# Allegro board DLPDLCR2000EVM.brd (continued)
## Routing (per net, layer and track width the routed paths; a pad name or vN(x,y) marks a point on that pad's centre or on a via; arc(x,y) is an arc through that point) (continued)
DATEN: length 43
  TOP w0.132: v2(24.5,33.76) 24.5,33.76 24.7,33.96 24.7,37.07 26.29,38.66 28.76,38.66 28.82,38.73 U12.G15
  BOTTOM w0.132: v2(24.5,33.76) 25.89,33.76 25.9,33.75 27.02,33.75 27.22,33.94 28.69,33.94 29.34,33.29 34.36,33.29 40.61,39.55 40.61,46.25 44.15,49.78 44.15,51.61 45.14,52.6 P1.30
DBIC_CSZ: length 6.3
  LY2 w0.102: 31.8,35.56 31.51,35.85 v1(31.51,36.73)
  LY2 w0.132: v3(31.51,34.44) 31.89,34.83 31.89,35.47 31.8,35.56
  LY3 w0.132: v4(31.5,31.32) 31.54,31.32 32.21,31.99 32.21,32.84 31.51,33.54 v3(31.51,34.44)
DMD_BUS: length 22.3
  TOP w0.132: R37.1 24.77,40.34 v4(24.51,40.08) ; v4(22.74,32.31) 22.6,32.16 J1.27
  LY3 w0.132: v4(22.74,32.31) 22.81,32.37 22.81,33.15 23.02,33.36 23.02,36.3 22.77,36.54 22.77,37.12 22.61,37.28 22.32,37.28 22.18,37.15 22.18,35.89 22.21,35.86 22.21,35.67 22.08,35.53 21.89,35.53 21.78,35.65 21.78,37.84 21.69,37.92 21.46,37.92 21.32,37.79 21.32,37.51 21.33,37.51 21.33,35.54 21.2,35.41 21.01,35.41 20.88,35.54 20.88,37.92 21.89,38.94 21.89,39.32 22.16,39.59 24.01,39.59 v4(24.51,40.08)
DMD_BUS_T: length 5.4
  LY3 w0.102: 28.73,40.11 28.81,40.11 28.93,39.99 29.97,39.99 v4(30.31,40.33)
  LY3 w0.132: v4(25.32,40.54) 28.24,40.54 28.67,40.11 28.73,40.11
DMD_D0: length 31.7
  TOP w0.132: v4(19.99,32.46) 17.86,32.46 17.65,32.66 J1.26 ; v4(22.53,33.4) 22.91,33.4 23.5,33.99 23.5,34.26 24.31,35.08 24.31,39.81 24.03,40.09 24.03,41.38 22.35,43.05 22.35,46.72 22.49,46.85 24.63,46.85 24.76,46.72 24.76,45.38 24.63,45.25 24.5,45.25 24.22,45.25 23.59,44.61 23.59,43.43 23.83,43.19 23.83,42.29 24.51,41.61 R11.1
  LY3 w0.132: v4(22.53,33.4) 20.93,33.4 v4(19.99,32.46)
DMD_D0_T: length 3.1
  TOP w0.132: R11.2 27.97,41.61 28.84,40.73 U12.M15
DMD_D1: length 22.4
  TOP w0.132: v4(20.87,39.18) 18.53,39.18 17.91,39.8 16.84,39.8 16.69,39.65 16.69,39.18 16.83,39.05 16.99,39.05 17.04,38.99 17.67,38.99 17.81,38.86 17.81,38.35 17.62,38.16 J1.4
  LY3 w0.132: v4(24.77,42.67) 24.77,42.44 24.59,42.27 23.93,42.27 23.8,42.13 23.8,40.17 23.71,40.08 23.52,40.08 23.43,40.17 23.43,42.53 23.98,43.08 23.98,44.14 23.85,44.27 23.47,44.27 22.61,43.41 22.61,41.29 21.3,39.98 21.3,39.85 20.87,39.42 v4(20.87,39.18)
DMD_D1_T: length 5.2
  LY3 w0.132: v4(29.91,41.13) 29.38,41.13 28.73,41.78 26.88,41.78 26.71,41.95 26.05,41.95 v4(25.32,42.67)
DMD_D2: length 22.9
  TOP w0.132: v4(19.94,36.86) 19.9,36.82 19.24,36.82 18.47,37.59 17.96,37.59 17.53,37.16 16.83,37.16 J1.8
  LY3 w0.132: v4(24.77,41.96) 24.23,41.96 24.08,41.81 24.08,40 23.91,39.83 23.32,39.83 23.18,39.97 23.18,42.64 23.73,43.18 23.73,43.71 23.6,43.85 23.4,43.85 23.29,43.74 23.29,43.31 22.85,42.88 22.85,41.19 21.54,39.88 21.54,39.75 21.21,39.41 21.21,38.96 20.29,38.05 20.14,38.05 19.94,37.85 19.94,37.54 20.35,37.13 20.35,35.89 20.21,35.76 19.94,35.76 19.8,35.89 19.8,36.24 19.94,36.37 v4(19.94,36.86)
DMD_D2_T: length 5.1
  LY3 w0.132: v4(25.32,41.96) 25.58,41.7 26.61,41.7 26.78,41.53 28.52,41.53 29.21,40.84 29.59,40.84 29.71,40.73 v4(29.91,40.73)
DMD_D3: length 24.3
  TOP w0.132: v4(26.19,42.32) 24.41,42.32 24.21,42.52 24.21,42.73 v4(24.12,42.81) ; J1.12 17.42,36.16 17.86,36.6 17.92,36.6 18.03,36.71 18.03,37.01 18.13,37.11 18.31,37.11 18.44,36.97 18.44,36.73 18.62,36.56 19.03,36.56 19.11,36.47 v4(19.59,36.47)
  LY3 w0.132: v4(19.59,36.47) 19.58,36.48 19.58,39.95 19.69,40.06 20,40.06 20.09,40.16 20.09,40.28 19.91,40.45 19.91,40.64 20.04,40.77 20.24,40.77 20.42,40.59 20.6,40.59 20.7,40.69 20.7,40.82 20.82,40.93 20.99,40.93 21,40.94 21.01,40.94 21.13,40.82 21.13,40.69 21.27,40.55 21.45,40.55 21.56,40.67 21.56,40.94 21.67,41.05 22.01,41.05 22.36,41.4 22.36,43.52 23.63,44.8 23.75,44.8 23.93,44.61 24.04,44.61 24.11,44.69 24.11,44.79 23.94,44.96 23.94,45.11 24.05,45.21 24.13,45.21 24.26,45.09 24.44,45.09 24.75,45.39 24.94,45.39 25.03,45.3 25.03,45.13 24.22,44.32 24.22,43.44 24.46,43.21 24.46,42.68 24.32,42.55 24.18,42.55 24.12,42.6 v4(24.12,42.81)
DMD_D3_T: length 3.3
  TOP w0.132: U12.N15 28.92,41.13 27.73,42.32 R10.2
DMD_D4: length 27.9
  TOP w0.132: v4(20.04,35.33) 19.99,35.38 17.81,35.38 17.52,35.66 J1.14 ; R13.1 27.41,45.67 27.06,45.67 26.8,45.41 26.8,45.2 26.3,44.7 26.07,44.7 25.77,45 25.77,47.56 25.45,47.88 21.69,47.88 21.35,47.53 21.35,42.64 22.89,41.09 v4(22.89,40.81)
  LY3 w0.132: v4(22.89,40.81) 22.89,40.54 22.78,40.44 22.61,40.44 21.56,39.4 21.56,38.96 20.62,38.02 20.62,35.53 20.42,35.33 v4(20.04,35.33)
DMD_D4_T: length 5.1
  LY3 w0.102: 29.16,42.67 v4(30.31,41.53)
  LY3 w0.132: v4(27.89,45.59) 27.89,43.95 29.16,42.67
DMD_D5: length 24
  TOP w0.132: v4(19.66,34.98) 19.64,35 18.91,35 18.84,34.92 18.84,34.59 18.76,34.52 18.65,34.52 18.58,34.59 18.58,34.9 18.5,34.98 18.39,34.98 18.32,34.9 18.32,34.59 18.24,34.52 18.01,34.52 17.88,34.65 17.88,34.98 17.81,35.05 17.67,35.05 17.55,35.16 J1.16
  LY3 w0.132: v4(24.77,43.38) 24.47,43.68 24.47,44.22 25.34,45.09 26.11,45.09 26.24,45.22 26.24,45.47 26.07,45.64 24.13,45.64 22.11,43.63 22.11,41.54 21.88,41.31 21.02,41.31 20.89,41.18 20.07,41.18 19.3,40.41 19.3,36.33 19.53,36.09 19.53,35.89 19.36,35.72 19.36,35.16 19.54,34.98 v4(19.66,34.98)
DMD_D5_T: length 5.4
  LY2 w0.102: v1(29.91,41.53) v3(29.41,41.53)
  LY3 w0.132: v4(25.32,43.38) 25.63,43.38 26.92,42.09 28.85,42.09 v3(29.41,41.53)
DMD_D6: length 30.8
  TOP w0.132: v4(19.13,32.82) 18.08,32.82 17.73,33.17 16.83,33.17 J1.24 ; v4(22.63,34.62) 22.63,34.62 23.21,34.62 23.98,35.38 23.98,39.62 23.72,39.88 23.72,39.92 23.69,39.95 23.69,41.24 22.02,42.91 22.02,47.05 22.15,47.18 24.94,47.18 25.1,47.02 25.1,45.04 24.97,44.91 24.36,44.91 23.92,44.47 23.92,43.57 24.46,43.03 R9.1
  LY3 w0.132: v4(22.63,34.62) 21.51,34.62 19.71,32.82 v4(19.13,32.82)
DMD_D6_T: length 3.4
  TOP w0.132: R9.2 27.49,43.03 28.99,41.53 U12.P15
DMD_D7: length 30.3
  TOP w0.132: R8.1 24.48,43.74 24.26,43.96 24.26,44.34 24.5,44.58 25.23,44.58 25.43,44.78 25.43,47.16 25.07,47.52 21.86,47.52 21.68,47.34 21.68,42.78 23.36,41.1 23.36,39.81 23.39,39.78 23.39,39.74 23.39,39.73 23.39,39.72 23.63,39.48 23.63,36 22.76,35.13 v4(22.66,35.13) ; J1.20 16.83,34.16 17.65,34.16 18.03,33.78 v4(19.25,33.78)
  LY3 w0.132: v4(19.25,33.78) 19.25,34.01 20.27,35.03 22.56,35.03 v4(22.66,35.13)
DMD_D7_T: length 3.5
  TOP w0.132: R8.2 27.25,43.74 29.07,41.93 U12.R15
DMD_D8: length 25.9
  TOP w0.132: J1.7 19.43,37.16 18.62,37.97 v4(18,37.97)
  LY3 w0.132: v4(28.96,44.73) 28.96,44.5 29.31,44.14 29.31,43.62 29.18,43.48 28.71,43.48 28.3,43.9 28.3,46.38 27.8,46.87 23.52,46.87 20.78,44.13 20.78,42.81 20.47,42.49 19.61,42.49 19.32,42.2 18.74,42.2 18,41.47 v4(18,37.97)
DMD_D8_T: length 3.3
  TOP w0.132: R16.2 28.96,43.71 29.43,43.24 30.02,43.24 30.71,42.55 U12.R12
DMD_D9: length 23.5
  TOP w0.132: v4(17.12,39.37) 17.83,39.37 19.04,38.16 J1.3
  LY3 w0.132: v4(30.02,46.15) 28.43,47.75 23.34,47.75 19.93,44.35 19.35,44.35 17.12,42.11 v4(17.12,39.37)
DMD_D9_T: length 6.5
  LY3 w0.102: 31.05,42.67 31.05,42.5 31.29,42.25 31.29,42.22 31.35,42.16 31.35,41.9 31.39,41.86 31.39,41.41 31.11,41.13 v4(31.11,41.13)
  LY3 w0.132: v4(30.02,45.59) 30.39,45.96 30.96,45.96 31.1,45.81 31.1,45.5 31.09,45.49 31.09,45.24 30.79,44.94 30.79,44.05 31.05,43.79 31.05,42.67
DMD_D10: length 24.8
  TOP w0.132: J1.13 21.08,35.66 21.03,35.72 18.03,35.72 v4(18.01,35.74)
  LY3 w0.132: v4(18.01,35.74) 17.42,36.32 17.42,41.83 18.29,42.7 19.05,42.7 19.99,43.64 19.99,44.05 23.3,47.37 28.1,47.37 v4(29.31,46.15)
DMD_D10_T: length 4.8
  LY3 w0.102: v4(31.11,41.53) 30.48,42.16 30.48,42.67
  LY3 w0.132: 30.48,42.67 30.48,43.67 30.02,44.13 30.02,44.89 v4(29.31,45.59)
DMD_D11: length 25.7
  TOP w0.132: v4(18.02,36.25) 18.11,36.25 18.14,36.22 18.89,36.22 18.99,36.12 19.71,36.12 19.81,36.22 21.47,36.22 J1.11
  LY3 w0.132: v4(18.02,36.25) 18.07,36.25 18.07,36.24 17.92,36.24 17.68,36.47 17.68,41.61 18.52,42.45 19.18,42.45 19.48,42.75 20.37,42.75 20.54,42.92 20.54,44.24 23.42,47.12 27.9,47.12 29,46.02 29,45.4 29.14,45.27 29.18,45.27 29.67,44.78 v4(29.67,44.73)
DMD_D11_T: length 3
  TOP w0.132: R18.2 29.67,43.84 29.9,43.61 30.12,43.61 31.11,42.63 U12.R11
DMD_D12: length 37
  LY3 w0.132: v2(18.15,28.38) 18.62,28.85 18.62,31.39 16.21,33.81 16.21,43.54 18.77,46.1 19.88,46.1 20.49,46.71 22.27,48.49 29.57,48.49 31.35,46.71 31.35,45.4 31.34,45.39 31.34,45.1 31.09,44.85 v4(31.09,44.73)
  BOTTOM w0.132: R105.2 v2(18.15,28.38)
DMD_D12_OPT: length 2.9
  TOP w0.132: J1.44 v2(15.24,28.16)
  BOTTOM w0.132: v2(15.24,28.16) 16.07,28.16 16.29,28.38 R105.1
DMD_D12_T: length 3.3
  LY3 w0.102: v4(31.51,41.13) 31.51,41.25 31.59,41.33 31.59,41.95 31.56,41.98 31.56,42.28 31.3,42.54 31.3,42.67
  LY3 w0.132: 31.3,42.67 31.3,43.96 v4(31.09,44.17)
DMD_D13: length 35.2
  TOP w0.132: v4(30.77,46.79) 30.77,46.74 30.78,46.73 R21.1
  LY3 w0.132: v2(18.16,27.66) 18.9,28.4 18.9,31.57 16.48,33.99 16.48,43.31 19.01,45.83 20.08,45.83 22.49,48.24 29.32,48.24 v4(30.77,46.79)
  BOTTOM w0.132: R106.2 v2(18.16,27.66)
DMD_D13_OPT: length 1.8
  TOP w0.132: J1.46 v2(15.75,27.66)
  BOTTOM w0.132: R106.1 16.47,27.66 v2(15.75,27.66)
DMD_D13_T: length 4.6
  LY2 w0.102: v3(31.01,42.14) 31.01,42.02 v1(31.51,41.53)
  LY3 w0.132: v3(31.01,42.14) 30.81,42.35 30.81,43.69 30.55,43.95 30.55,45.41 30.73,45.59 v4(30.78,45.59)
DMD_D14: length 36.3
  TOP w0.132: v4(30.14,46.77) 30.38,46.54 30.38,46.41 30.38,46.41 30.38,45.89 30.38,45.89 30.38,45.85 30.38,45.85 30.38,45.34 30.38,45.33 R20.1
  LY3 w0.132: v4(30.14,46.77) 28.92,48 22.59,48 20.18,45.59 19.27,45.59 16.74,43.05 16.74,34.14 19.18,31.7 19.18,27.97 v2(18.15,26.94)
  BOTTOM w0.132: R113.2 v2(18.15,26.94)
DMD_D14_OPT: length 3
  TOP w0.132: J1.48 v2(15.21,27.16)
  BOTTOM w0.132: v2(15.21,27.16) 15.44,26.94 R113.1
DMD_D14_T: length 2.7
  TOP w0.132: R20.2 30.38,43.84 31.51,42.71 U12.R10
DMD_DCLK: length 22.2
  TOP w0.132: J1.17 v4(19.25,34.66)
  LY3 w0.132: v4(19.25,34.66) 19.23,34.66 19.05,34.85 19.05,40.57 19.71,41.22 19.73,41.22 19.93,41.42 20.79,41.42 21,41.63 21.77,42.41 21.77,43.64 24.02,45.89 26.17,45.89 26.42,45.64 26.7,45.64 26.87,45.48 26.87,45.18 26.87,45.18 26.87,44.96 26.72,44.81 25.48,44.81 v4(24.77,44.09)
DMD_DCLK_T: length 6.2
  LY3 w0.102: 28.73,42.39 29.04,42.39 v4(30.31,41.13)
  LY3 w0.132: 28.73,42.39 27.18,42.39 25.48,44.09 v4(25.32,44.09)
DMD_LOADB: length 26.4
  TOP w0.132: v4(27.17,45.23) 27.17,45.23 27.17,45.14 27.18,45.13 28.11,45.13 28.24,44.99 R14.1 ; 20.13,34.16 20.13,34.17 v2(20.13,34.17) ; 20.13,34.16 v4(18.42,34.16) ; 20.13,34.16 J1.19
  LY3 w0.132: v4(18.42,34.16) 18.42,33.78 18.31,33.68 18.17,33.68 18.03,33.81 18.03,34.8 18.56,35.32 18.56,41.17 19.11,41.71 19.52,41.71 19.73,41.92 20.59,41.92 21.28,42.61 21.28,43.88 21.42,44.02 23.78,46.38 27.03,46.38 27.17,46.25 27.17,45.23 v4(27.17,45.23)
  BOTTOM w0.132: v2(20.13,34.17) 20.13,34.17 20.13,34.16 R109.1
DMD_LOADB_T: length 3.6
  TOP w0.132: U12.R13 30.31,42.46 29.87,42.9 29.04,42.9 28.24,43.7 R14.2
DMD_OEZ: length 30.1
  TOP w0.132: v2(23.24,30.15) 23.23,30.16 J1.35
  LY3 w0.102: v4(30.31,40.73) 30.3,40.73 29.77,40.19 29.02,40.19 28.73,40.48
  LY3 w0.132: v2(23.24,30.15) 23.55,29.84 23.55,28.97 23.47,28.9 22.55,28.9 22.48,28.82 22.48,28.71 22.55,28.64 23.47,28.64 23.55,28.56 23.55,28.02 23.74,27.82 23.93,27.82 25.05,28.94 25.05,32.4 24.9,32.56 24.29,32.56 23.77,33.08 23.77,37.21 22.86,38.13 22.86,38.72 22.99,38.85 24.62,38.85 25.16,39.39 25.16,40.19 25.03,40.32 25.03,40.66 25.2,40.83 28.38,40.83 28.73,40.48
  BOTTOM w0.132: v2(23.24,30.15) 23.23,30.16 21.9,30.16 R108.1
DMD_SAC_BUS: length 24.6
  TOP w0.132: v4(23.39,32.65) 23.38,32.66 23.19,32.66 23.09,32.56 23.09,31.3 22.96,31.16 J1.31 ; R38.1 26.19,40.84 25.86,40.51 25.86,40.43 25.56,40.13 25.48,40.13 v4(24.86,39.51)
  LY3 w0.132: v4(23.39,32.65) 23.33,32.58 23.33,31 23.8,30.53 23.8,28.58 23.93,28.45 24.19,28.45 24.81,29.07 24.81,32.16 24.66,32.31 23.91,32.31 23.77,32.44 23.77,32.73 23.53,32.97 23.53,32.99 23.52,32.99 23.52,37.12 22.53,38.11 22.53,38.89 22.74,39.1 24.44,39.1 v4(24.86,39.51)
DMD_SAC_BUS_T: length 3
  TOP w0.132: R38.2 28.2,40.89 28.77,40.33 U12.L15
DMD_SAC_CLK: length 22.7
  LY3 w0.132: v2(20.04,27.97) 20.32,28.24 20.73,28.24 20.96,28.02 20.96,26.7 21.09,26.57 21.74,26.57 21.87,26.7 21.87,29.95 22.1,30.18 22.68,30.18 23.06,30.56 23.06,32.99 23.27,33.2 23.27,37.02 22.62,37.67 22.33,37.67 22.2,37.8 22.2,39.21 22.33,39.34 24.27,39.34 24.8,39.87 24.8,40.2 24.77,40.24 v4(24.77,41.25)
  BOTTOM w0.132: v2(20.04,27.97) 20.04,28.02 20.18,28.16 R114.1
DMD_SAC_CLK_OPT: length 2.8
  TOP w0.132: J1.43 v2(23.11,28.16)
  BOTTOM w0.132: v2(23.11,28.16) 21.89,28.16 R114.2
DMD_SAC_CLK_T: length 5
  LY2 w0.102: v1(29.91,40.33) 29.38,40.33 v3(29.24,40.47)
  LY3 w0.132: v4(25.32,41.25) 28.32,41.25 29.1,40.47 v3(29.24,40.47)
DMD_SCTRL: length 25.9
  TOP w0.132: v4(18.39,33.35) 18.58,33.16 J1.23
  LY3 w0.132: v4(27.53,44.73) 27.53,46.49 27.4,46.63 23.64,46.63 21.03,44.02 21.03,42.71 20.48,42.16 19.63,42.16 19.42,41.96 18.95,41.96 18.31,41.33 18.31,35.48 17.75,34.92 17.75,33.68 18.08,33.35 v4(18.39,33.35)
DMD_SCTRL_T: length 3.6
  TOP w0.132: R12.2 27.53,43.93 29.05,42.42 29.67,42.42 29.91,42.18 U12.R14
DMD_STRB: length 23.8
  TOP w0.132: v4(19.89,31.11) 19.89,30.41 19.71,30.23 19.71,29.64 19.56,29.49 18.8,29.49 18.62,29.67 18.62,31.34 18.29,31.67 16.84,31.67 J1.30 ; v4(24.08,34.21) 24.08,34.21 24.08,33.38 23.93,33.22 23.56,33.22 23.56,33.23 23.28,33.23 22.84,32.79 v4(22.51,32.79)
  LY3 w0.132: v4(19.89,31.11) 20.32,31.11 20.8,31.6 20.8,32.05 21.13,32.38 22.1,32.38 v4(22.51,32.79) ; v4(26.19,40.18) 26.57,39.8 26.57,39.16 25.75,38.34 25.75,37.82 24.94,37.01 24.69,37.01 24.21,37.49 24.21,38.47 24.07,38.6 23.69,38.6 23.5,38.41 23.5,37.86 24.08,37.29 24.08,34.21 v4(24.08,34.21)
DMD_STRB_T: length 3.8
  LY3 w0.102: v4(30.31,39.93) 30.17,39.79
  LY3 w0.132: v4(26.75,40.18) 28.25,40.18 28.64,39.79 28.83,39.79 28.84,39.77 30.06,39.77 30.08,39.79 30.17,39.79
DMD_TRC: length 28.1
  TOP w0.132: v4(26.47,46.05) 26.95,46.05 27.42,46.52 28.23,46.52 R15.1
  LY3 w0.132: v4(26.47,46.05) 26.38,46.13 23.88,46.13 21.52,43.78 21.52,42.51 20.69,41.67 19.83,41.67 19.63,41.47 19.34,41.47 18.81,40.93 18.81,32.43 19.43,31.8 19.43,27.91 v2(20.19,27.15)
  BOTTOM w0.132: R115.1 v2(20.19,27.15)
DMD_TRC_OPT: length 2.9
  TOP w0.132: J1.47 v2(23.14,27.16)
  BOTTOM w0.132: R115.2 21.89,27.16 v2(23.14,27.16)
DMD_TRC_T: length 5
  LY3 w0.102: v4(30.71,41.53) 29.62,42.62 29.62,42.67
  LY3 w0.132: v4(28.6,45.59) 28.76,45.44 28.76,45.3 29.03,45.02 29.08,45.02 29.37,44.73 29.37,44.59 29.62,44.35 29.62,42.67
DMD_VBIAS: length 5.6
  TOP w0.132: R68.2 13.36,31.37 13.56,31.17 TP17.1 14.1,31.16 v2(15.24,31.16) J1.32
  BOTTOM w0.132: C124.1 16.47,31.16 v2(15.24,31.16)
DMD_VOFS: length 4.3
  TOP w0.132: R107.2 TP16.1 v2(23.91,31.66) ; J1.29 v2(22.6,31.66)
  BOTTOM w0.132: v2(23.91,31.66) v2(22.6,31.66) 21.9,31.66 C127.1
DMD_VRST: length 5.5
  TOP w0.132: R69.2 13.36,28.96 13.56,29.16 TP18.1 14.1,29.16 v2(15.24,29.16) J1.40
  BOTTOM w0.132: v2(15.24,29.16) 15.25,29.16 C125.1
DPP_CMP_PWM: length 41.8
  TOP w0.132: v4(33.2,33.98) 32.78,33.57 v4(32.78,32.11) ; R85.1 v2(56.78,23.81)
  LY2 w0.102: v1(32.71,36.73) 32.71,36.15 v3(32.95,35.91)
  LY3 w0.132: v3(32.95,35.91) 32.95,35.63 32.98,35.6 32.98,35.23 33.25,34.96 33.25,34.04 v4(33.2,33.98) ; v4(32.78,32.11) 32.78,30.27 32.35,29.84 32.35,26.5 31.18,25.33 31.18,23.97 v2(32.6,22.55) ; v2(56.78,23.81) 52.24,23.81 51.29,22.87 v2(36.61,22.87)
  BOTTOM w0.132: v2(36.61,22.87) 36.16,23.32 33.36,23.32 v2(32.6,22.55)
DPP_PLLI: length 6.1
  TOP w0.132: v2(27.69,39.75) 27.86,39.93 U12.K15
  BOTTOM w0.132: XD100.3 23.64,39.84 C111.2 24.68,39.83 25.1,39.83 25.29,40.02 R101.1 27.42,40.02 v2(27.69,39.75)
DPP_PLLO: length 11.5
  TOP w0.132: v2(26.18,39.44) 27.44,39.44 27.52,39.35 28.37,39.35 28.54,39.53 U12.J15
  BOTTOM w0.132: R102.1 24.24,36.59 26.18,38.52 v2(26.18,39.44) 26.46,39.44 R101.2
DPP_SPICLK: length 3.1
  TOP w0.132: U12.A4 33.91,35.69 35.31,34.28 R78.2
DPP_SPICSZ0: length 2.9
  TOP w0.132: U12.A5 33.51,35.41 34.36,34.56 R76.2
DPP_SPICSZ1: length 6.6
  TOP w0.132: R75.2 34.16,31.66 v4(34.5,32)
  LY3 w0.132: v4(33.11,37.13) 33.11,36.87 33.78,36.2 33.78,35.47 33.99,35.27 33.99,33.62 34.5,33.1 v4(34.5,32)
DPP_SPIDOUT: length 6.8
  TOP w0.132: v4(35.5,32.08) 35.31,31.88 R77.2
  LY3 w0.102: v4(33.51,37.13) 33.51,36.98 34.49,36 34.49,35.56
  LY3 w0.132: 34.49,35.56 34.49,34.84 35.5,33.82 v4(35.5,32.08)
FLEX_TP: length 7.1
  TOP w0.254: TP26.1 36.42,19.14 36.42,18.77 36.61,18.58 v2(37.04,18.58) ; JLEDFLEX.5 v2(41.34,18.58)
  BOTTOM w0.254: v2(41.34,18.58) v2(37.04,18.58)
FLSH_1P8V: length 13.8
  TOP w0.305: v2(55.96,29.58) 55.94,29.59 U3.8
  TOP w0.381: U3.3 50.38,27.05 51.65,28.32 U3.7 55.94,28.32 v2(55.96,28.33) v2(55.96,29.58)
  BOTTOM w0.305: C123.1 55.07,29.58 v2(55.96,29.58)
  BOTTOM w0.381: R103.2 C123.1
G[0]: length 39
  TOP w0.132: U12.D15 28.23,37.53 27.7,37 27.7,35.94 27,35.24 27,34.72 26.56,34.28 26.56,33.88 26.04,33.35 v2(26.04,33.35)
  BOTTOM w0.132: P1.13 22.81,48.16 18.03,48.16 15.27,45.39 15.27,37.39 15.52,37.13 16.63,37.13 18.77,34.99 23.47,34.99 23.88,34.59 23.88,33.5 24.03,33.35 v2(26.04,33.35)
G[1]: length 47.2
  LY2 w0.102: v3(29.44,37.28) 29.62,37.28 29.87,37.53 v1(29.91,37.53)
  LY3 w0.102: v3(29.44,37.28) 29.37,37.28 28.73,36.64
  LY3 w0.132: v2(25.85,30.51) 25.86,30.51 25.86,30.51 26.52,30.51 28.08,32.06 28.08,32.83 28.1,32.86 28.1,34.74 28.04,34.8 28.04,35.95 28.73,36.64
  BOTTOM w0.132: P1.12 23.23,51.75 23.23,49.77 22.29,48.83 17.64,48.83 14.54,45.73 14.54,36.39 15.03,35.9 16.92,35.9 19.71,33.11 19.71,31.29 19.91,31.09 23.27,31.09 23.85,30.51 25.86,30.51 25.86,30.51 v2(25.85,30.51)
G[2]: length 57.1
  TOP w0.132: U12.C15 28.6,37.13 28.04,36.56 28.04,35.8 27.8,35.57 27.8,34.27 27.16,33.63 26.92,33.63 26.23,32.94 26.23,31.71 v2(26.22,31.7)
  BOTTOM w0.132: v2(26.22,31.7) 26.23,31.7 26.23,31.14 26.52,30.84 28.15,29.21 28.42,29.21 28.59,29.04 29.51,29.04 30.08,28.47 35.04,28.47 36.1,29.53 38.14,29.53 44.1,35.49 44.1,36.77 46.13,38.8 46.13,42.7 50.41,46.97 53.53,46.97 55.59,49.04 58.06,49.04 58.84,49.82 58.84,51.17 P1.42
G[3]: length 50.8
  LY2 w0.102: v3(29.33,36.85) 29.57,36.85 29.85,37.13 v1(29.91,37.13)
  LY3 w0.132: v3(29.33,36.85) 28.29,35.81 28.29,34.91 28.35,34.84 28.35,32.75 28.32,32.73 28.32,31.74 v2(27.67,31.08)
  BOTTOM w0.132: P1.39 56.88,51.12 54.9,51.12 54.34,50.56 54.34,49.93 52.07,47.66 50.14,47.66 45.19,42.7 45.19,38.84 42.41,36.06 42.41,35.49 37.11,30.2 35.53,30.2 35.02,29.68 32.95,29.68 32.49,29.23 30.42,29.23 29.94,29.71 28.86,29.71 28.69,29.88 28.46,29.88 27.67,30.68 v2(27.67,31.08)
G[4]: length 49.3
  LY3 w0.102: 29.09,35.56 30.17,36.65 30.17,36.84 30.31,36.97 v4(30.31,37.13)
  LY3 w0.132: v2(28.24,30.66) 29.16,31.58 29.16,32.77 28.84,33.09 28.84,35.32 29.09,35.56
  BOTTOM w0.132: v2(28.24,30.66) 28.69,30.22 28.83,30.22 29,30.05 34.91,30.05 35.53,30.67 36.35,30.67 44.81,39.12 44.81,42.79 50.3,48.29 52.23,48.29 54.01,50.06 54.01,50.7 54.76,51.46 56.19,51.46 57.44,52.7 P1.40
G[5]: length 48.2
  TOP w0.132: v2(26.69,31.23) 27.26,31.8 27.26,33.21 28.14,34.09 28.14,35.43 28.37,35.66 28.37,36.42 28.68,36.73 U12.B15
  BOTTOM w0.132: v2(26.69,31.23) 26.69,31.18 28.32,29.55 28.56,29.55 28.73,29.38 29.72,29.38 30.28,28.81 33.24,28.81 33.75,29.32 35.13,29.32 35.67,29.87 37.25,29.87 42.74,35.36 42.74,35.9 45.54,38.7 45.54,42.58 50.28,47.32 52.45,47.32 P1.37
G[6]: length 43.8
  LY2 w0.102: v1(29.91,36.73) 29.91,36.4 29.81,36.3 29.81,36.29 29.8,36.28 29.8,36.05 29.82,36.03 29.82,35.84 v3(29.59,35.61)
  LY3 w0.102: 29.54,35.56 v3(29.59,35.61)
  LY3 w0.132: v2(29.32,30.79) 29.45,30.92 29.45,32.86 29.09,33.22 29.09,35.11 29.54,35.56
  BOTTOM w0.132: P1.38 54.18,51.58 52.83,51.58 51.31,50.07 51.31,49.91 50.43,49.02 50.09,49.02 44.11,43.05 44.11,39.38 36.07,31.34 35.25,31.34 34.63,30.72 29.61,30.72 29.53,30.79 v2(29.32,30.79)
G[7]: length 41.4
  TOP w0.132: U12.A15 28.66,35.48 28.66,35.47 28.48,35.29 28.48,33.69 v2(27.66,32.87)
  BOTTOM w0.132: P1.36 51.88,52.7 50.84,51.66 50.36,51.66 48.63,49.93 48.63,49.77 42.72,43.86 42.72,39.76 34.35,31.39 29.88,31.39 29.44,31.83 28.43,31.83 27.87,32.39 27.87,32.66 v2(27.66,32.87)
GPIO1_RPWM: length 5
  LY3 w0.132: v4(33.1,45.8) 32.68,45.38 32.68,44.75 32.41,44.48 32.41,42.09 32.31,41.99 v4(32.31,41.13)
GPIO2_GPWM: length 5.5
  LY2 w0.102: v3(31.6,42.63) 31.6,42.62 31.76,42.46 31.76,42.07 31.91,41.92 v1(31.91,41.53)
  LY3 w0.132: v4(32.59,46.43) 31.91,45.75 31.91,45.61 31.58,45.28 31.58,42.65 v3(31.6,42.63)
GPIO3_BPWM: length 2.7
  TOP w0.132: U12.R8 32.31,43.13 32.08,43.36 TP4.1
GPIO4: length 62.7
  TOP w0.132: U8.2 48.84,9.65 v2(48.67,9.83)
  LY3 w0.132: v4(31.91,37.13) 31.91,36.75 32.42,36.24 32.42,35.84 32.39,35.81 32.39,34.91 v2(32.61,34.7) 32.61,33.49 33.47,32.63 33.47,28.84 33.43,28.81 33.43,28.19 33.66,27.97 33.66,17.45 37.01,14.1 46.18,14.1 48.67,11.61 v2(48.67,9.83)
  BOTTOM w0.132: P1.26 38.56,51.21 38.56,39.41 33.84,34.7 v2(32.61,34.7)
GPIO5: length 68.6
  LY2 w0.102: v1(31.91,36.73) 31.91,36.18 v3(32.12,35.96)
  LY3 w0.102: 32.12,35.56 v3(32.12,35.96)
  LY3 w0.132: 32.12,35.56 32.12,33.62 33.08,32.67 33.08,29.77 32.68,29.37 32.68,28.38 33.26,27.79 33.26,27.46 32.6,26.8 32.6,25.93 v2(31.57,24.91)
  BOTTOM w0.132: P1.18 28.94,53.66 21.88,53.66 21.32,53.1 21.32,52.92 19.62,51.23 16.64,51.23 16.1,50.69 16.1,49.45 13.87,47.22 13.87,35.99 14.66,35.2 16.66,35.2 18.95,32.92 18.95,29.92 19.79,29.08 20.35,29.08 20.52,28.91 25.83,28.91 27.06,27.68 27.97,27.68 29.76,25.89 30.39,25.89 31.37,24.91 v2(31.57,24.91)
GRN_CATHODE: length 11.8
  LY3 w0.254: v4(64.45,19.58) 64.3,19.58 63.85,19.14 62.25,19.14 61.53,18.41
  LY3 w0.508: TP30.1 61.53,18.41
  vias: v2(40.64,19.84) v2(41.2,19.84) v2(41.73,19.84)
HOST_PRESENTZ: length 14.9
  TOP w0.132: U10.3 60.06,7.17 60.68,6.55 64.29,6.55 ; 64.29,6.55 65.72,7.99 U11.3 66.5,9.04 66.64,9.18 R97.1 ; 64.29,6.55 64.29,3.28 P2.43
HSYNC: length 41.4
  LY3 w0.132: v2(25.65,32.8) 25.65,32.79 25.66,32.8 25.68,32.8 25.68,32.8 25.61,32.87 25.61,33.34 25.15,33.8 25.15,36.51 26.47,37.83 26.72,37.83 28.16,39.27 28.73,39.27 28.87,39.13 v4(30.31,39.13)
  BOTTOM w0.132: P1.29 41.02,46.05 41.02,39.48 34.5,32.96 29.2,32.96 28.55,33.6 27.36,33.6 27.16,33.41 26.66,33.41 26.04,32.8 25.68,32.8 25.68,32.8 25.66,32.8 25.65,32.79 v2(25.65,32.8)
HWTEST_EN: length 2.5
  TOP w0.132: U12.A9 31.91,35.03 31.81,34.94 R72.1
JTAG_TCK: length 6.6
  LY2 w0.102: v1(33.51,41.13) v3(33.9,41.13)
  LY3 w0.102: v3(33.9,41.13) 33.81,41.13 33.63,41.31 33.63,41.64 33.79,41.81 33.91,41.81 34.35,42.26 34.35,42.32 34.7,42.67
  LY3 w0.132: v4(37.47,44.96) 37.47,44.4 36.29,43.22 35.25,43.22 34.7,42.67
JTAG_TDI: length 6
  LY2 w0.102: v1(33.11,41.53) 33.11,41.85 33.01,41.94 33.01,41.97 v3(33,41.99)
  LY3 w0.102: 33.25,42.67 33.24,42.66 33.24,42.61 33.24,42.61 33.24,42.57 33.19,42.53 33.19,42.52 33.19,42.51 33.19,42.17 33.03,42.01 33.02,42.01 v3(33,41.99)
  LY3 w0.132: 33.25,42.67 33.25,44.15 33.9,44.8 33.9,46.85 v4(34.11,47.07)
JTAG_TDO: length 2.8
  TOP w0.132: TP8.1 32.71,44.14 U12.R7
JTAG_TMS: length 4.4
  LY3 w0.102: 32.99,42.67 32.99,42.6 32.99,42.6 32.99,42.37 32.71,42.09 v4(32.71,41.13)
  LY3 w0.132: 32.99,42.67 32.99,44.36 33.17,44.55 33.17,44.73 v4(33.6,45.16)
JTAGTRSTZ: length 10.9
  TOP w0.132: v4(35.05,44.56) TP12.1
  LY2 w0.102: v1(32.31,41.53) 32.31,41.91 v3(32.04,42.18)
  LY3 w0.132: v4(35.05,44.56) 35.05,46.54 34.23,47.36 33.92,47.36 32.88,46.33 32.88,46.31 32.43,45.86 32.43,44.85 32.16,44.58 32.16,42.3 v3(32.04,42.18)
L1: length 0.4
  TOP w0.203: U5.B2 U5.B1
L2: length 0.4
  TOP w0.203: U5.D1 U5.D2
LED_ANODE: length 3.4
  TOP w0.203: 64.01,21.58 64.01,21.58 U5.G1 U5.G2 ; U5.G2 U5.F2 U5.E2 U5.E1 ; U5.G2 64.05,21.18 64.03,21.17 ; U5.G2 U5.G3 64.01,20.78 64.01,20.79
  TOP w0.381: 62.49,23.88 C26.1
  vias: v2(63.37,23.89) v2(63.37,22.62) v2(63.42,21.46)
LED_ENABLE: length 2.7
  TOP w0.132: U12.A11 31.11,35.81 30.7,35.4 30.7,34.53 30.86,34.36 R70.2
LED_SEL_0: length 65.4
  TOP w0.132: U12.R6 33.11,42.71 33.63,43.23 33.63,44.55 34.21,45.14 34.21,46.23 35.84,47.86 57.26,47.86 v2(58.9,46.22)
  LY2 w0.102: v3(64.32,21.67) 64.85,21.14 v1(64.85,20.78)
  LY3 w0.132: v3(64.32,21.67) 63.87,22.12 v2(56.2,22.12)
  BOTTOM w0.132: v2(56.2,22.12) 56.21,22.13 56.21,24.94 57.21,25.94 57.21,44.17 58.9,45.86 v2(58.9,46.22)
LED_SEL_1: length 72.7
  LY2 w0.102: v1(65.25,20.78) 65.25,21.23 v3(65.03,21.44)
  LY3 w0.102: v4(33.11,41.13) 33.11,41.7 33.39,41.98 33.39,42.44 33.63,42.67
  LY3 w0.132: v2(59.75,45.75) 59.3,46.21 59.3,46.38 58.72,46.96 53.02,46.96 51.41,48.58 51.41,52.86 51.17,53.09 51.17,53.1 50.49,53.78 39.25,53.78 38.65,53.18 38.65,49.54 35.35,46.23 35.35,44.42 35.16,44.24 34.05,44.24 33.67,43.86 33.67,42.71 33.63,42.67 ; v3(65.03,21.44) 64.32,22.16 64.32,22.47 63.68,23.1 v2(59.57,23.1)
  BOTTOM w0.132: v2(59.75,45.75) 59.75,44.7 60.16,44.29 60.16,32.72 59.28,31.83 59.28,23.4 v2(59.57,23.1)
LEDDRV_ON: length 5.3
  LY2 w0.102: v1(32.71,41.53) v3(32.71,42.49)
  LY3 w0.132: v4(33.6,46.43) 33.39,46.22 33.39,45.67 32.93,45.21 32.93,44.65 32.71,44.43 32.71,42.49 v3(32.71,42.49)
MEM0_A0: length 17.7
  TOP w0.132: v4(57.47,41.46) 57.44,41.46 U13.J8
  LY3 w0.132: v4(57.47,41.46) 57.47,42.72 56.81,43.38 54.27,43.38 53.71,43.94 49.14,43.94 48.63,44.45 44.26,44.45 43.04,43.23 v4(42.73,43.23)
MEM0_A1: length 18.2
  TOP w0.132: U13.J9 57.11,44.7 55.64,46.18 51.78,46.18 51.27,46.69 44.74,46.69 R30.1
MEM0_A2: length 20.1
  LY3 w0.132: v4(57.91,40.99) 57.91,42.79 57.06,43.64 54.52,43.64 53.96,44.2 49.29,44.2 48.73,44.76 44.06,44.76 42.84,43.54 v4(40.9,43.54)
MEM0_A3: length 19.8
  TOP w0.132: v4(58.22,42.09) 58.21,42.09 U13.K8
  LY3 w0.132: v4(40.9,44.25) 42.94,44.25 43.75,45.06 48.83,45.06 49.42,44.48 54.13,44.48 54.66,43.94 57.2,43.94 58.22,42.92 v4(58.22,42.09)
MEM0_A4: length 19.4
  TOP w0.102: v4(58.23,36.68) 58.22,36.68 U13.K2
  LY3 w0.132: v4(58.23,36.68) 58.13,36.68 54.83,33.38 43.24,33.38 42.74,33.88 41.52,33.88 41.42,33.78 v4(40.9,33.78)
MEM0_A5: length 19.4
  LY3 w0.132: v4(40.9,34.49) 42.94,34.49 43.45,33.99 49.44,33.99 50.15,34.7 55.33,34.7 56.96,36.32 56.96,36.83 57.16,37.03 57.71,37.03 57.91,37.23 v4(57.91,37.79)
MEM0_A6: length 19.5
  TOP w0.132: U13.J1 57.11,35.06 57.23,34.95 v4(57.23,34.59)
  LY3 w0.132: v4(57.23,34.59) 56.82,34.19 56.45,34.19 56.24,33.97 56.24,33.63 56.31,33.55 56.31,33.07 56.01,32.77 41.21,32.77 v4(40.9,33.07)
MEM0_A7: length 16.8
  TOP w0.102: v4(57.47,36.63) 57.47,36.63 U13.J2
  LY3 w0.132: v4(57.47,36.63) 57.47,36.42 54.72,33.68 43.35,33.68 42.84,34.19 v4(42.73,34.19)
MEM0_A8: length 17.1
  LY3 w0.132: v4(42.73,35.61) 42.74,35.61 43.75,34.6 49.14,34.6 50.56,36.02 54.93,36.02 55.23,35.71 55.54,35.71 56.25,36.42 56.25,37.69 56.35,37.79 v4(57.11,37.79)
MEM0_A9: length 19.4
  TOP w0.102: U13.H1 56.31,35.38
  TOP w0.132: v4(56.55,33.78) 56.31,34.02 56.31,35.38
  LY3 w0.132: v4(40.9,32.36) 41.11,32.36 41.21,32.46 56.14,32.46 56.67,32.99 56.67,33.67 v4(56.55,33.78)
MEM0_A10: length 17.6
  TOP w0.132: U13.J7 57.17,40.99 v4(57.47,40.69)
  LY3 w0.132: v4(42.73,42.52) 43.35,42.52 44.67,43.84 48.32,43.84 48.93,43.23 49.75,43.23 50.15,42.83 56.25,42.83 57.16,41.91 57.16,41 v4(57.47,40.69)
MEM0_A11: length 17.3
  TOP w0.132: U13.H2 56.72,36.58 56.72,34.95 56.66,34.89 v4(56.66,34.6)
  LY3 w0.132: v4(42.71,33.48) 43.12,33.07 54.93,33.07 56.45,34.6 v4(56.66,34.6)
MEM0_A12: length 16.6
  TOP w0.102: U13.H3 56.66,37.45 v4(56.66,37.44)
  LY3 w0.132: v4(42.73,34.9) 42.94,34.9 43.55,34.29 49.24,34.29 49.95,35 55.23,35 56.66,36.42 v4(56.66,37.44)
MEM0_A13: length 1.1
  TOP w0.102: U13.F7 v2(54.71,40.38)
  BOTTOM w0.102: R100.1 54.72,40.39 v2(54.71,40.38)
MEM0_BA0: length 19.3
  LY3 w0.132: v4(40.9,41.3) 41.41,41.81 43.55,41.81 44.97,43.23 48.12,43.23 48.73,42.62 49.14,42.62 49.54,42.22 55.64,42.22 55.74,42.11 55.74,40.69 55.84,40.59 56.25,40.59 56.31,40.66 v4(56.31,41.79)
MEM0_BA1: length 18.9
  TOP w0.184: U13.H9 v4(56.66,42.93)
  LY3 w0.132: v4(40.9,42.83) 41,42.93 43.24,42.93 44.46,44.15 48.53,44.15 49.04,43.64 50.25,43.64 50.38,43.51 50.38,43.23 50.48,43.13 50.86,43.13 50.97,43.23 50.97,43.54 51.07,43.64 51.88,43.64 51.99,43.52 51.99,43.23 52.1,43.13 52.49,43.13 52.59,43.23 52.59,43.44 52.79,43.64 53.51,43.64 53.71,43.44 53.71,43.23 53.81,43.13 56.45,43.13 v4(56.66,42.93)
MEM0_CASZ: length 19.7
  TOP w0.132: v4(56.66,44.45) 56.66,43.54 55.88,42.77 55.88,42.16 U13.G8
  LY3 w0.132: v4(56.66,44.45) 55.44,45.67 41.61,45.67 v4(40.9,44.96)
MEM0_CKE: length 19.3
  LY3 w0.132: v4(40.9,35.82) 41.11,36.02 43.75,36.02 43.96,35.82 43.96,35.21 44.26,34.9 49.04,34.9 50.46,36.32 54.72,36.32 55.13,36.73 55.13,37.54 55.33,37.75 55.84,37.75 55.94,37.64 55.94,36.63 55.51,36.2 v4(55.51,36.19)
MEM0_CLK_N: length 20.8
  TOP w0.102: R55.1 41.16,37.06 43.06,37.06 46.97,33.16 54.75,33.16 55.3,33.7 55.3,34.13 R67.1 55.3,34.45 55.3,35.75 55.12,35.92 55.12,37.4 U13.G3
MEM0_CLK_P: length 20.5
  TOP w0.102: R56.1 41.14,36.78 42.95,36.78 46.85,32.88 54.87,32.88 55.58,33.59 55.58,34.13 R67.2 55.58,34.45 55.58,35.64 55.9,35.96 55.9,36.6 U13.G2
MEM0_CSZ: length 18.2
  TOP w0.132: U13.H7 56.34,40.99 v4(56.66,41.3)
  LY3 w0.132: v4(40.9,42.11) 43.35,42.11 44.77,43.54 48.22,43.54 48.83,42.93 49.54,42.93 49.95,42.52 56.15,42.52 56.66,42.01 v4(56.66,41.3)
MEM0_DQ0: length 9.1
  TOP w0.132: U12.N1 38.55,41.13 39.13,41.71 41.14,41.71 41.6,42.17 43.24,42.17 43.28,42.22 R35.1
MEM0_DQ1: length 13.4
  LY2 w0.102: v3(34.96,40.73) v1(34.71,40.73)
  LY3 w0.102: 36.03,40.9 35.34,40.9 35.17,40.73 v3(34.96,40.73)
  LY3 w0.132: 36.03,40.9 36.13,41 36.13,41.36 36.28,41.5 36.49,41.5 36.64,41.36 36.64,41 36.74,40.9 37.05,40.9 37.15,41 37.15,41.36 37.3,41.5 37.51,41.5 37.66,41.36 37.66,41 37.75,40.91 38.07,40.91 38.18,41.01 38.18,41.42 38.27,41.5 38.57,41.5 38.67,41.4 38.67,41 38.77,40.9 39.08,40.9 39.18,41 39.18,41.4 39.28,41.5 39.48,41.5 39.69,41.3 39.69,41 39.84,40.84 42.26,40.84 42.34,40.77 43.01,40.77 43.35,41.1 v4(44.06,41.1)
MEM0_DQ2: length 7.5
  TOP w0.132: U12.M1 38.87,40.73 39.09,40.94 41.14,40.94 42.01,41.81 R33.1
MEM0_DQ3: length 8
  LY3 w0.102: 35.81,40.59 35.79,40.61 35.38,40.61 35.1,40.33 v4(34.31,40.33)
  LY3 w0.132: 35.81,40.59 40.06,40.59 40.26,40.39 v4(42.13,40.39)
MEM0_DQ4: length 9.7
  LY2 w0.102: v1(34.71,40.33) 35.1,40.33 35.1,40.33 35.33,40.33 35.34,40.33 v3(35.57,40.33)
  LY3 w0.132: v3(35.57,40.33) 39.91,40.33 40.26,39.98 43.04,39.98 43.45,40.39 v4(44.06,40.39)
MEM0_DQ5: length 7.6
  LY2 w0.102: v3(35.22,40.05) 34.83,40.05 v1(34.71,39.93)
  LY3 w0.102: 35.81,40.05 35.79,40.03 35.24,40.03 v3(35.22,40.05)
  LY3 w0.132: 35.81,40.05 39.69,40.05 40.06,39.68 v4(42.13,39.68)
MEM0_DQ6: length 7.4
  TOP w0.132: R45.1 41.8,41.1 41.29,40.59 39.24,40.59 38.98,40.33 U12.L1
MEM0_DQ7: length 5.3
  TOP w0.132: R41.1 39.62,40.18 39.36,39.93 U12.K1
MEM0_DQ8: length 8.1
  LY2 w0.102: v3(35.52,39.29) 34.87,39.29 v1(34.71,39.13)
  LY3 w0.132: v3(35.52,39.29) 35.93,39.29 37.17,38.05 41.62,38.05 41.82,38.25 v4(42.13,38.25)
MEM0_DQ9: length 10
  LY3 w0.132: v4(34.71,38.73) 36.03,38.73 37.01,37.75 41.92,37.75 42.13,37.95 43.35,37.95 43.65,38.25 v4(44.06,38.25)
MEM0_DQ10: length 18.5
  LY3 w0.102: v4(34.31,39.13) 34.91,39.13 35.33,39.55 35.41,39.55 35.43,39.57 35.71,39.57 35.74,39.55 36.34,39.55
  LY3 w0.132: v4(44.06,38.96) 43.55,38.96 43.19,38.61 41.47,38.61 41.21,38.36 40.6,38.36 40.5,38.46 40.5,38.86 40.4,38.96 40.2,38.96 40.09,38.86 40.09,38.4 39.99,38.3 39.79,38.3 39.69,38.4 39.69,39.17 39.59,39.27 39.38,39.27 39.28,39.17 39.28,38.46 39.18,38.36 38.98,38.36 38.88,38.46 38.88,39.37 38.77,39.47 38.57,39.47 38.47,39.37 38.47,38.46 38.37,38.36 38.16,38.36 38.06,38.46 38.06,39.37 37.96,39.47 37.76,39.47 37.66,39.37 37.66,38.47 37.54,38.36 37.37,38.36 37.25,38.47 37.25,39.37 37.15,39.47 36.94,39.47 36.84,39.37 36.84,39.19 36.72,39.07 36.56,39.07 36.44,39.19 36.44,39.45 36.34,39.55
MEM0_DQ11: length 10.5
  LY3 w0.102: 35.81,38.05 35.37,38.05 35.09,38.33 34.51,38.33 v4(34.31,38.33)
  LY3 w0.132: v4(44.06,37.44) 44.06,37.44 43.65,37.03 36.85,37.03 35.81,38.05
MEM0_DQ12: length 5.3
  TOP w0.132: U12.F1 39.08,38.33 39.36,38.05 R44.1
MEM0_DQ13: length 9.9
  LY2 w0.102: v3(35.07,37.93) v1(34.71,37.93)
  LY3 w0.132: v4(44.06,36.73) 36.7,36.73 35.62,37.8 35.35,37.8 35.33,37.82 35.18,37.82 v3(35.07,37.93)
MEM0_DQ14: length 7.8
  LY2 w0.102: v1(34.71,38.33) 35.41,38.33 35.43,38.35 v3(35.46,38.35)
  LY3 w0.132: v4(42.13,37.44) 36.84,37.44 35.92,38.35 v3(35.46,38.35)
MEM0_DQ15: length 16.5
  LY3 w0.102: 35.98,36.86 35.24,37.6 34.86,37.6 34.54,37.93 v4(34.31,37.93)
  LY3 w0.132: 35.98,36.86 35.98,35.85 36.11,35.71 36.3,35.71 36.44,35.85 36.44,36.32 36.54,36.42 36.8,36.42 36.94,36.28 36.94,35.56 37.09,35.41 37.3,35.41 37.45,35.56 37.45,36.28 37.6,36.42 37.81,36.42 37.96,36.28 37.96,35.56 38.11,35.41 38.32,35.41 38.47,35.56 38.47,36.28 38.62,36.42 38.83,36.42 38.98,36.28 38.98,35.56 39.13,35.41 39.34,35.41 39.48,35.56 39.48,36.28 39.63,36.42 39.84,36.42 39.99,36.28 39.99,35.56 40.14,35.41 40.35,35.41 40.5,35.56 40.5,36.12 40.7,36.32 v4(42.13,36.32)
MEM0_LDM: length 21.5
  TOP w0.132: U13.F8 54.49,41.79 54.29,41.59 54.29,40.36 53.71,39.78 47.21,39.78 46.8,40.18 46.8,43.03 46.6,43.23 46.19,43.23 45.99,43.03 45.99,40.49 45.53,40.03 41.85,40.03 41.29,39.47 R42.1
MEM0_LDQS: length 9.9
  LY2 w0.102: v1(34.71,39.53) 34.88,39.7 v3(35.01,39.7)
  LY3 w0.102: 35.79,39.8 35.38,39.8 35.33,39.75 35.06,39.75 v3(35.01,39.7)
  LY3 w0.132: 35.79,39.8 39.46,39.8 39.99,39.27 43.05,39.27 43.46,39.68 v4(44.06,39.68)
MEM0_RASZ: length 17.7
  TOP w0.132: U13.G9 55.51,42.93 56.25,43.67 56.25,44.96 55.44,45.77 51.58,45.77 51.07,46.28 45.07,46.28 42.74,43.94 R34.1
MEM0_UDM: length 20.6
  TOP w0.132: R48.1 43.07,39.32 53.86,39.32 54.22,39.68 57.27,39.68 57.47,39.48 57.47,39.06 57.27,38.86 54.62,38.86 54.31,38.55 54.31,37.39 U13.F2
MEM0_UDQS: length 5.2
  TOP w0.132: U12.G1 40.29,38.73 R43.1
MEM0_WEZ: length 17.3
  TOP w0.132: v4(55.88,44.25) 55.88,43.88 55.13,43.13 55.13,41.37 U13.G7
  LY3 w0.132: v4(42.73,45.37) 48.93,45.37 49.55,44.74 54.33,44.74 54.83,44.25 v4(55.88,44.25)
MEM_T_A0: length 7.7
  TOP w0.132: U12.P1 38.28,41.53 39.93,43.18 41.46,43.18 41.51,43.23 R31.2
MEM_T_A1: length 9.1
  TOP w0.132: R30.2 41.68,44.65 41.64,44.62 39.5,44.62 37.53,42.65 34.74,42.65 34.31,42.22 U12.R3
MEM_T_A2: length 5.9
  TOP w0.132: R26.2 39.58,43.54 37.97,41.93 U12.R1
MEM_T_A3: length 6.7
  TOP w0.132: U12.R2 34.71,42.18 34.84,42.31 37.81,42.31 39.75,44.25 R25.2
MEM_T_A4: length 6.3
  TOP w0.132: U12.A1 36.63,36.33 39.18,33.78 R79.2
MEM_T_A5: length 6.1
  TOP w0.132: U12.B1 36.95,36.73 39.18,34.49 R59.2
MEM_T_A6: length 7.1
  TOP w0.132: R80.2 39.18,33.07 36.34,35.92 34.87,35.92 34.71,36.08 U12.A2
MEM_T_A7: length 9
  LY2 w0.102: v3(34.96,36.73) v1(34.71,36.73)
  LY3 w0.132: v3(34.96,36.73) 34.96,35.82 36.59,34.19 v4(42.13,34.19)
MEM_T_A8: length 9.4
  LY2 w0.102: v3(34.99,37.32) 34.92,37.32 v1(34.71,37.53)
  LY3 w0.102: 35.52,35.95 35.52,37.03 35.24,37.32 v3(34.99,37.32)
  LY3 w0.132: v4(42.13,35.61) 42.03,35.71 41.31,35.71 40.7,35.1 36.37,35.1 35.52,35.95
MEM_T_A9: length 8
  TOP w0.132: U12.A3 34.31,35.82 34.77,35.36 36.29,35.36 39.28,32.36 R81.2
MEM_T_A10: length 7.8
  LY3 w0.132: v4(34.71,41.53) 35.66,42.48 37.16,42.48 37.2,42.52 v4(42.13,42.52)
MEM_T_A11: length 9.5
  LY2 w0.102: v1(34.31,36.73) 34.44,36.6 v3(34.44,36.46)
  LY3 w0.132: v3(34.44,36.46) 34.73,36.17 34.73,35.7 36.95,33.48 v4(42.13,33.48)
MEM_T_A12: length 9.6
  LY3 w0.102: v4(34.31,37.53) 34.8,37.03 35.12,37.03 35.28,36.87
  LY3 w0.132: v4(42.13,34.9) 42.06,34.83 36.29,34.83 35.28,35.85 35.28,36.87
MEM_T_BA0: length 6.7
  LY3 w0.102: 35.83,41.81 35.04,41.02 34.6,41.02 v4(34.31,40.73)
  LY3 w0.132: 35.83,41.81 39.59,41.81 40.09,41.3 v4(40.3,41.3)
MEM_T_BA1: length 6.5
  LY3 w0.132: v4(34.31,41.53) 34.41,41.63 34.41,41.65 35.49,42.73 37.06,42.73 37.15,42.83 v4(40.3,42.83)
MEM_T_CASZ: length 7.9
  TOP w0.132: U12.R4 33.91,42.29 34.6,42.98 37.38,42.98 39.35,44.96 R24.2
MEM_T_CKE: length 6.4
  TOP w0.132: R58.2 40.3,35.79 R57.2 38.68,35.82 37.37,37.13 U12.C1
MEM_T_CLK_N: length 5.7
  TOP w0.102: U12.E1 35.44,37.93 35.5,37.87 38.07,37.87 38.85,37.08 40.08,37.08 40.32,37.33 R55.2
MEM_T_CLK_P: length 5.7
  TOP w0.102: U12.D1 35.44,37.53 35.5,37.59 37.95,37.59 38.73,36.8 40.04,36.8 R56.2
MEM_T_CSZ: length 8.3
  LY3 w0.102: 35.71,42.11 34.82,41.22 34.41,41.22 34,40.81 34,39.84 v4(34.31,39.53)
  LY3 w0.132: 35.71,42.11 v4(40.3,42.11)
MEM_T_DQ0: length 17.7
  TOP w0.132: U13.A8 51.14,42.22 51.14,45.6 50.86,45.87 49.34,45.87 49.14,45.67 49.14,44.76 48.93,44.55 48.63,44.55 48.43,44.76 48.43,45.67 48.22,45.87 45.17,45.87 44.36,45.06 44.36,44.76 44.36,44.75 44.36,44.45 44.16,44.25 43.65,44.25 43.45,44.05 43.45,43.33 43.65,43.13 44.26,43.13 44.36,43.03 44.36,42.82 44.34,42.8 R35.2
MEM_T_DQ1: length 14.2
  TOP w0.132: U13.B7 51.09,40.56 47.84,40.56 47.61,40.79 47.61,44.45 47.41,44.65 45.37,44.65 45.17,44.45 45.17,41.3 44.97,41.1 R50.2
MEM_T_DQ2: length 18.6
  TOP w0.132: U13.B8 51.51,41.75 51.17,41.4 49.75,41.4 49.44,41.71 49.44,42.62 49.24,42.83 48.42,42.83 48.22,43.03 48.22,43.34 48.42,43.54 49.67,43.54 49.85,43.72 49.85,43.97 49.67,44.15 48.22,44.15 48.02,44.35 48.02,45.26 47.82,45.47 45.29,45.47 44.77,44.95 44.77,42.01 44.57,41.81 R33.2
MEM_T_DQ3: length 18.5
  LY3 w0.132: v4(52.31,40.99) 52.31,41.27 52.08,41.5 48.85,41.5 48.73,41.39 48.73,41.22 48.85,41.1 51.74,41.1 51.88,40.96 51.88,40.77 51.74,40.63 47.78,40.63 47.61,40.79 47.61,41.46 47.46,41.61 47.25,41.61 47.1,41.46 47.1,40.79 47,40.69 43.35,40.69 43.04,40.39 v4(42.75,40.39)
MEM_T_DQ4: length 15.9
  TOP w0.132: v4(52.69,40.59) 52.69,41.41 U13.C8
  LY3 w0.132: v4(52.69,40.59) 52.79,40.49 53.3,40.49 53.4,40.39 53.4,39.88 53.3,39.78 51.89,39.78 51.78,39.89 51.78,40.18 51.68,40.29 51.27,40.29 51.17,40.18 51.17,39.89 51.06,39.78 50.66,39.78 50.55,39.89 50.55,40.18 50.45,40.29 50.03,40.29 49.93,40.18 49.93,39.89 49.81,39.78 49.34,39.78 49.24,39.88 49.24,40.18 49.14,40.29 48.79,40.29 48.68,40.18 48.68,39.89 48.57,39.78 48.18,39.78 48.06,39.89 48.06,40.1 47.88,40.29 47.62,40.29 47.44,40.1 47.44,39.89 47.32,39.78 46.93,39.78 46.82,39.89 46.82,40.27 46.7,40.39 46.31,40.39 46.19,40.27 46.19,39.89 46.08,39.78 45.69,39.78 45.57,39.89 45.57,40.27 45.46,40.39 v4(44.64,40.39)
MEM_T_DQ5: length 18.4
  LY3 w0.132: v4(53.11,40.99) 53.11,41.32 53.2,41.4 53.51,41.4 53.71,41.2 53.71,40.54 53.86,40.39 54.07,40.39 54.22,40.54 54.22,41.2 54.42,41.4 54.83,41.4 55.13,41.1 55.13,39.68 54.93,39.47 45.42,39.47 44.91,39.98 43.41,39.98 43.1,39.68 v4(42.75,39.68)
MEM_T_DQ6: length 20.2
  LY3 w0.132: v4(42.75,41.1) 43.16,41.5 44.56,41.5 44.77,41.71 44.77,42.68 44.92,42.83 45.13,42.83 45.28,42.68 45.28,41.15 45.42,41 45.64,41 45.78,41.15 45.78,42.78 45.93,42.93 46.14,42.93 46.29,42.78 46.29,41.25 46.44,41.1 46.65,41.1 46.8,41.25 46.8,42.78 46.95,42.93 47.16,42.93 47.31,42.78 47.31,42.26 47.46,42.11 47.67,42.11 47.82,42.26 47.82,42.58 47.96,42.72 48.18,42.72 48.32,42.58 48.32,41.99 48.53,41.79 v4(53.11,41.79)
MEM_T_DQ7: length 20.6
  TOP w0.132: U13.E7 53.91,40.8 53.3,40.18 47.61,40.18 47.21,40.59 47.21,44.05 47.01,44.25 45.78,44.25 45.58,44.05 45.58,41.08 45.23,40.74 41.93,40.74 41.38,40.18 R41.2
MEM_T_DQ8: length 18.9
  LY3 w0.132: v4(42.73,38.25) 43.24,38.25 43.55,38.56 51.47,38.56 51.88,38.15 51.88,36.78 52.03,36.63 52.24,36.63 52.39,36.78 52.39,38.41 52.54,38.56 52.75,38.56 52.9,38.41 52.9,36.78 53.04,36.63 53.26,36.63 53.4,36.78 53.4,38.41 53.55,38.56 53.76,38.56 53.91,38.41 v4(53.91,37.79)
MEM_T_DQ9: length 16.5
  TOP w0.132: U13.D2 52.72,37.39 52.72,38.03 52.13,38.61 49.6,38.61 49.44,38.45 49.44,37.54 49.24,37.34 48.91,37.34 48.73,37.52 48.73,38.38 48.55,38.56 48.32,38.56 48.12,38.36 48.12,37.44 47.92,37.24 47.61,37.24 47.41,37.44 47.41,38.29 47.21,38.49 46.9,38.49 46.7,38.29 46.7,36.93 46.5,36.73 46.19,36.73 45.99,36.93 45.99,38.05 45.79,38.25 R54.2
MEM_T_DQ10: length 9.4
  TOP w0.132: U13.D3 53.11,38.54 52.68,38.98 46.47,38.98 46.45,38.96 R53.2
MEM_T_DQ11: length 15.8
  TOP w0.132: U13.C2 51.91,36.59 51.33,36.59 51.12,36.38 51.12,35.95 51.27,35.79 51.27,34.85 51.17,34.75 50.3,34.75 49.64,34.09 48.22,34.09 48.02,34.29 48.02,36.12 47.82,36.32 47.51,36.32 47.31,36.12 47.31,34.8 47.11,34.6 46.83,34.6 46.63,34.8 46.63,35.72 46.43,35.92 45.52,35.92 45.17,36.26 45.17,37.24 44.97,37.44 R65.2
MEM_T_DQ12: length 20.8
  TOP w0.132: R44.2 41.08,37.85 45.37,37.85 45.58,37.64 45.58,36.52 45.78,36.32 46.9,36.32 47.31,36.73 48.23,36.73 48.43,36.53 48.43,34.79 48.62,34.6 48.89,34.6 49.08,34.79 49.08,36.77 49.25,36.93 49.48,36.93 49.64,36.77 49.64,35.28 49.82,35.1 50.08,35.1 50.25,35.28 50.25,37.14 50.5,37.38 51.91,37.38 U13.C3
MEM_T_DQ13: length 17.4
  LY3 w0.132: v4(44.66,36.73) 44.97,36.42 48.58,36.42 48.73,36.27 48.73,36.06 48.58,35.92 45.2,35.92 45.07,35.79 45.07,35.61 45.2,35.48 48.7,35.48 49.24,36.02 49.24,37.24 49.34,37.34 49.64,37.34 49.75,37.24 49.75,36.93 49.9,36.78 50.15,36.78 50.27,36.9 50.27,37.24 50.41,37.37 51.13,37.37 v4(51.51,36.99)
MEM_T_DQ14: length 19.3
  LY3 w0.132: v4(42.73,37.44) 43.35,37.44 43.75,37.85 44.87,37.85 45.07,37.64 45.07,36.88 45.22,36.73 45.43,36.73 45.58,36.88 45.58,38.15 45.68,38.25 46.09,38.25 46.19,38.15 46.19,36.88 46.34,36.73 46.55,36.73 46.7,36.88 46.7,38.05 46.9,38.25 47.1,38.25 47.31,38.05 47.31,36.88 47.46,36.73 47.67,36.73 47.82,36.88 47.82,38.05 48.02,38.25 48.22,38.25 48.43,38.05 48.43,36.98 48.57,36.83 48.78,36.83 48.93,36.98 48.93,38.15 49.04,38.25 51.07,38.25 51.51,37.81 v4(51.51,37.79)
MEM_T_DQ15: length 9.5
  LY3 w0.132: v4(50.71,36.99) 48.93,35.21 44.46,35.21 44.26,35.41 44.26,35.92 43.85,36.32 v4(42.73,36.32)
MEM_T_LDM: length 5.2
  TOP w0.132: R42.2 39.14,39.47 39.09,39.53 U12.J1
MEM_T_LDQS: length 16.6
  LY3 w0.132: v4(44.64,39.68) 45.15,39.17 56.25,39.17 56.45,39.37 56.45,39.98 56.25,40.18 55.64,40.18 55.44,40.39 55.44,41.4 55.03,41.81 53.94,41.81 v4(53.91,41.79)
MEM_T_RASZ: length 9.2
  LY3 w0.102: v4(33.91,41.53) 33.98,41.6 33.99,41.6 34.57,42.19
  LY3 w0.132: 34.57,42.19 35.36,42.98 36.96,42.98 37.07,43.09 39.07,43.09 39.93,43.94 v4(42.15,43.94)
MEM_T_UDM: length 7.1
  TOP w0.132: U12.H1 41.58,39.13 41.74,38.96 R48.2
MEM_T_UDQS: length 21.8
  LY3 w0.132: v4(53.91,36.99) 54.17,36.99 55.39,38.2 57.48,38.2 57.67,38.4 57.67,38.67 57.48,38.86 44.67,38.86 44.26,39.27 43.41,39.27 43.1,38.96 41.11,38.96 v4(40.9,38.76)
MEM_T_WEZ: length 10.4
  TOP w0.132: U12.R5 33.51,42.45 34.38,43.32 37.21,43.32 39.27,45.37 42.15,45.37 R29.2
P1P0V: length 32.2
  TOP w0.102: v4(30.71,39.53) 30.99,39.25 30.99,39.21 31.01,39.19 31.01,38.51 30.83,38.33 U12.F12 ; v4(31.91,37.53) 31.91,37.53 32.19,37.81 33.23,37.81 U12.D5
  TOP w0.152: 32.31,40.7 32.31,40.66 32.05,40.41 31.62,40.41 v2(31.34,40.13) ; 32.31,40.7 32.58,40.42 32.83,40.42 33.01,40.6 ; 32.31,40.7 U12.M8 ; 33.01,40.6 33.01,40.01 33.5,39.52 ; 33.01,40.6 33.01,40.63 U12.M6 ; 33.5,39.52 33.5,38.33 ; 33.5,39.52 33.51,39.53 U12.J4 ; 33.5,38.33 U12.F4 ; 33.5,38.33 33.5,38.16 33.51,38.15 U12.D5
  TOP w0.203: v2(31.34,40.13) 31.34,40.14 31.11,40.37 U12.M11 ; R2.2 17.44,43.04 v2(17.53,43.13)
  TOP w0.254: v2(25.91,36.71) 26.5,36.71 C13.1 C14.1
  TOP w0.381: TP2.1 20.24,44.39 ; TP2.1 19.13,45.5 ; TP2.1 20.24,45.5 ; TP2.1 19.13,44.39
  LY3 w0.127: v4(30.71,39.53) 30.74,39.53 31.34,40.13 v2(31.34,40.13)
  LY4 w0.381: v2(20.14,43.15) 20.75,42.55 23.88,42.55 25.15,41.27 25.15,38.23 25.91,37.47 v2(25.91,36.71)
  BOTTOM w0.381: 19.13,44.39 TP2.1 ; TP2.1 20.24,45.5 ; TP2.1 19.13,45.5 ; TP2.1 20.24,44.39 ; v2(25.91,36.71) 25.92,36.7 F101.1
  vias: v2(18.16,43.77) v2(18.47,46.53) v2(18.69,47.02) v2(18.85,43.13) v2(19.1,46.53) v2(19.35,47.02) v2(19.51,43.76) v2(19.74,46.53) v2(19.99,47.02)
P1P0V_FB: length 3
  TOP w0.132: R1.1 13.54,42.9 U1.4 R2.1
P1P8V: length 66.8
  TOP w0.102: U12.M5 33.51,40.41 v2(33.43,40.34) 33.44,40.33 U12.L4 ; U12.M5 U12.L4 ; U12.M5 U12.N4 ; U12.L4 U12.K3
  TOP w0.127: v2(32.08,39.9) 31.86,39.9 31.68,39.72 31.39,39.72 31.35,39.68 31.06,39.68 31.01,39.73 30.99,39.73 30.79,39.93 U12.K12
  TOP w0.203: v2(35.56,24.14) 35.47,24.05 R84.2 ; U12.N12 v4(30.71,40.73)
  TOP w0.229: v2(19.87,33.56) 19.98,33.66 J1.21 ; J1.42 v2(15.75,28.66) ; J1.41 v2(19.86,28.66) ; J1.1 v2(20.19,38.66) ; J1.22 v2(15.76,33.66) ; J1.2 v2(15.75,38.66)
  TOP w0.3: 51.77,35.15 51.77,35.93 U13.B1 ; C3.1 50.71,44.5 U13.A9 ; C5.1 53.91,44.55 U13.E9 ; 52.31,44.15 U13.C9 ; 54.71,44.07 U13.F9
  TOP w0.305: v6(52.49,45.16) 52.28,44.95 C4.1 52.31,44.52 52.31,44.15 ; v2(59.77,41.88) 59.75,41.9 C7.1 59.19,42.56 59.17,42.59 U13.K9 ; v6(50.56,45.21) 50.66,45.12 C3.1 ; 51.77,35.15 C15.1 v2(52.55,34.29) C16.1 53.21,36.09 U13.D1 ; U13.A7 48.88,40.99 C10.1 48.34,41.04 v6(48.18,41.2) ; 54.71,44.07 54.73,44.09 C6.1 54.73,44.75 v6(54.32,45.16) 53.91,44.75 C5.1
  TOP w0.381: 37.17,26.51 TP23.1 ; TP23.1 38.27,26.51 ; TP23.1 38.27,25.41 ; TP23.1 37.17,25.41 ; v2(15.75,38.66) 15.09,38.66 C126.1 ; R70.1 v2(30.86,32.12) ; U11.6 v2(63.82,12.59) ; C17.1 59.09,36.75 v2(59,36.83) ; v2(30.85,29.62) 31.5,30.27 R71.2 ; U11.4 v2(65.72,12.59)
  LY3 w0.102: v2(33.43,40.34) 33.45,40.34 33.51,40.28 33.51,39.53 v4(34.31,38.73)
  LY3 w0.152: v4(34.31,38.73) 34.21,38.63 34.18,38.63 33.91,38.36 v4(33.91,37.93) v4(33.91,37.13) 33.81,37.22 33.81,37.25 33.54,37.53 v4(33.11,37.53) v4(32.31,37.53) ; v2(32.08,39.9) 32.08,40.08 31.91,40.25 v4(31.91,40.73) v4(30.71,40.73)
  LY3 w0.203: v2(69.76,20.68) 69.06,19.98 v4(66.45,19.98)
  LY4 w0.381: TP23.1 38.27,26.51 ; TP23.1 37.17,25.41 ; TP23.1 37.17,26.51 ; TP23.1 38.27,25.41
  BOTTOM w0.102: C102.1 33.57,40.21 33.45,40.34 v2(33.43,40.34)
  BOTTOM w0.381: v2(22.6,34.01) 22.61,34.01 22.61,34.06 22.5,34.16 R109.2 ; R104.1 v2(47.03,30.38) ; R110.1 v2(58.8,28.57) ; R116.1 69.46,20.38 v2(69.76,20.68) ; v2(65.72,12.59) 65.19,12.05 64.35,12.05 v2(63.82,12.59) ; R103.1 53.38,30.86 v2(53.37,30.87) ; R108.2 v2(20.19,30.15) ; C130.1 67.98,19.27 67.77,19.06 v2(67.39,19.06)
  BOTTOM w0.508: v2(21.08,26.07) 21.08,26.06 C128.1
  vias: v2(36.37,24.03) v2(36.51,27.24) v2(36.61,28.18) v2(36.7,24.9) v2(37.04,24.04) v2(37.57,28.17) v2(37.57,27.23) v2(37.85,24.14) v2(38.28,28.17) v2(38.3,27.25)
P1P8V_FB: length 3
  TOP w0.132: R83.1 31.57,23.91 U2.4 R84.1
P2P5V: length 19.6
  TOP w0.381: v2(39.23,9.27) 39.25,9.26 U6.5 ; U8.5 51.48,11.31 v2(51.75,11.58) 55.8,15.63 55.8,16.61 58.09,18.9 60.2,18.9 60.41,19.11 R90.1
  TOP w0.508: D2.2 v2(33.72,12.69)
  BOTTOM w0.381: C132.1 v2(51.75,11.58) ; v2(39.23,9.27) C134.1
  vias: v2(46.85,11.28) v2(47.31,10.87) v2(47.76,11.28)
PARKZ: length 61.8
  LY2 w0.102: v1(32.31,36.73) 32.31,36.31 32.51,36.11 32.51,36.07 32.57,36 32.57,35.6 32.61,35.56
  LY2 w0.132: 32.61,35.56 v3(32.68,35.48)
  LY3 w0.132: v2(68.82,21.13) 68.07,20.38 v4(66.45,20.38) ; v3(32.68,35.48) 32.68,35.18 33,34.86 33,34.53 32.9,34.43 32.9,33.59 33.72,32.78 33.72,30.06 34.7,29.08 34.7,28.25 34.32,27.87 34.32,23.22 v2(34.62,22.92)
  BOTTOM w0.132: v2(34.62,22.92) 34.62,19.84 38.73,15.72 51.54,15.72 52.14,15.13 63.36,15.13 63.7,15.47 63.7,18.71 64.19,19.2 64.19,19.82 64.75,20.38 R116.2 68.72,21.12 68.81,21.12 v2(68.82,21.13)
PCLK: length 22.2
  LY3 w0.102: 33.96,42.67 33.96,42.65 33.62,42.31 33.62,41.92 33.43,41.73 33.43,41.05 33.22,40.85 33.22,40.85 32.82,40.45 32.82,38.48 32.37,38.03 31.65,38.03 31.58,38.1 30.88,38.1 30.31,37.53 v4(30.31,37.53)
  LY3 w0.132: 33.96,42.67 33.96,42.77 34.97,43.78 35.09,43.78 35.65,44.34 36.03,44.34 36.4,44.71 36.4,45.52 39.34,48.47 40.45,48.47 41.23,49.24 41.23,51.34 P1.28
PDM_CVS_TE: length 4.6
  TOP w0.132: U12.H15 28.65,39.13 28.52,39 25.55,39 25.42,38.86 TP15.1
PROJ_ON: length 32.3
  TOP w0.132: U6.2 43.65,9.91 v2(43.68,9.93) ; U10.4 60.07,9.85 60.07,10.44 59.64,10.87 v2(58.85,10.87)
  LY2 w0.102: v3(65.1,19.18) 65.25,19.33 v1(65.25,19.58)
  LY3 w0.132: v3(65.1,19.18) 65.1,18.67 63.65,17.22 62.38,17.22 58.85,13.69 v2(58.85,10.87) 58.62,11.1 53.49,11.1 51.79,9.4 48.51,9.4 47.68,10.24 43.98,10.24 v2(43.68,9.93)
PROJ_ON_EXT: length 38.1
  TOP w0.132: U10.1 58.76,6.24 v2(58.97,6.03)
  LY3 w0.132: v2(58.97,6.03) 59.18,5.82 59.18,3.63 58.65,3.1 36.6,3.1 35.93,2.43 35.93,1.51 35.37,0.95 28.31,0.95 P2.15
PROJ_ON_S/A: length 2.5
  TOP w0.132: U9.2 57.48,10.61 58.27,9.83 58.75,9.83 U10.6
PWM_IN: length 12.4
  TOP w0.132: v2(59.42,19.68) 59.01,19.68 R87.2
  LY3 w0.132: v2(62.36,16.15) 63.09,16.89 64.18,16.89 65.48,18.19 65.48,18.97 65.65,19.14 v4(65.65,19.98)
  BOTTOM w0.132: v2(59.42,19.68) 59.42,17.52 60.78,16.15 v2(62.36,16.15)
PWR_EN: length 122.2
  TOP w0.132: v2(10.01,43.05) 10.02,43.04 U1.3 ; U2.3 28.05,24.05 v2(28.04,24.07)
  LY2 w0.102: v3(65.24,21.85) 65.65,21.44 v1(65.65,20.78)
  LY3 w0.132: v2(28.85,9.14) 28.85,14.38 28.14,15.09 28.14,18.19 27.23,19.1 27.23,20.57 28.04,21.39 v2(28.04,24.07) 28.77,24.8 28.77,27.13 28.26,27.64 25.89,27.64 22.31,24.07 13.78,24.07 12.88,24.97 12.88,40.64 11.58,41.93 11.13,41.93 v2(10.01,43.05) ; v3(65.24,21.85) 65.24,22.49 66.95,24.2 v2(68.69,24.2)
  BOTTOM w0.132: v2(68.69,24.2) 70.65,24.2 72.34,22.5 72.34,16.89 66.86,11.4 53.61,11.4 52.97,12.04 46.01,12.04 45.17,11.2 41.42,11.2 40.56,10.33 30.04,10.33 v2(28.85,9.14)
PWR_SUPERVISOR: length 1.7
  TOP w0.132: U9.3 v2(53.21,9.66)
  BOTTOM w0.132: v2(53.21,9.66) R125.1
R[0]: length 64.8
  TOP w0.132: v2(26.79,29.44) 26.79,30.77 28.13,32.1 28.13,32.69 28.82,33.39 28.82,35.05 29.91,36.13 U12.A14
  LY3 w0.132: v2(26.79,29.44) 22.02,24.66 14.25,24.66 13.44,25.48 13.44,42.89 18.48,47.93 21.04,47.93 22.02,48.91 27.75,48.91 28.47,49.63 28.47,51 28.08,51.38 26.14,51.38 P1.14
R[1]: length 46.9
  LY2 w0.102: v1(30.31,36.73) 30.31,36.45 30.09,36.23 30.09,36.16 v3(30.08,36.16)
  LY3 w0.102: v3(30.08,36.16) 29.89,35.97 29.89,35.56
  LY3 w0.132: 29.89,35.56 29.89,35.46 29.36,34.93 29.36,33.3 29.73,32.93 29.73,30.64 29.18,30.09 v2(26.37,30.09)
  BOTTOM w0.132: P1.11 21.28,49.16 17.43,49.16 14.2,45.94 14.2,36.19 14.83,35.56 16.78,35.56 19.3,33.04 19.3,30.12 20.01,29.42 20.48,29.42 20.63,29.27 25.18,29.27 26.01,30.09 v2(26.37,30.09)
R[2]: length 59.9
  TOP w0.132: U12.A13 30.31,36.06 29.16,34.91 29.16,31.52 28.81,31.18 28.81,30.63 v2(27.43,29.25)
  LY3 w0.132: P1.15 26.38,49.18 21.81,49.18 20.88,48.25 18.29,48.25 13.16,43.12 13.16,25.15 13.89,24.41 22.28,24.41 26.41,28.55 26.73,28.55 v2(27.43,29.25)
R[3]: length 59.1
  LY3 w0.102: v4(30.71,37.13) 30.71,36.78 30.38,36.45 30.38,35.76
  LY3 w0.132: 30.38,35.76 30.29,35.68 30.29,33.68 29.97,33.36 29.97,30.15 29.56,29.75 29.56,29 v2(28.89,28.33)
  BOTTOM w0.132: v2(28.89,28.33) 28.89,27.98 29.99,26.88 30.48,26.88 30.8,26.56 38.17,26.56 39.21,27.6 39.21,28.52 48.15,37.47 48.15,40.35 51.78,43.98 53.72,43.98 54.79,45.06 54.79,45.2 56.87,47.27 62.57,47.27 P1.45
